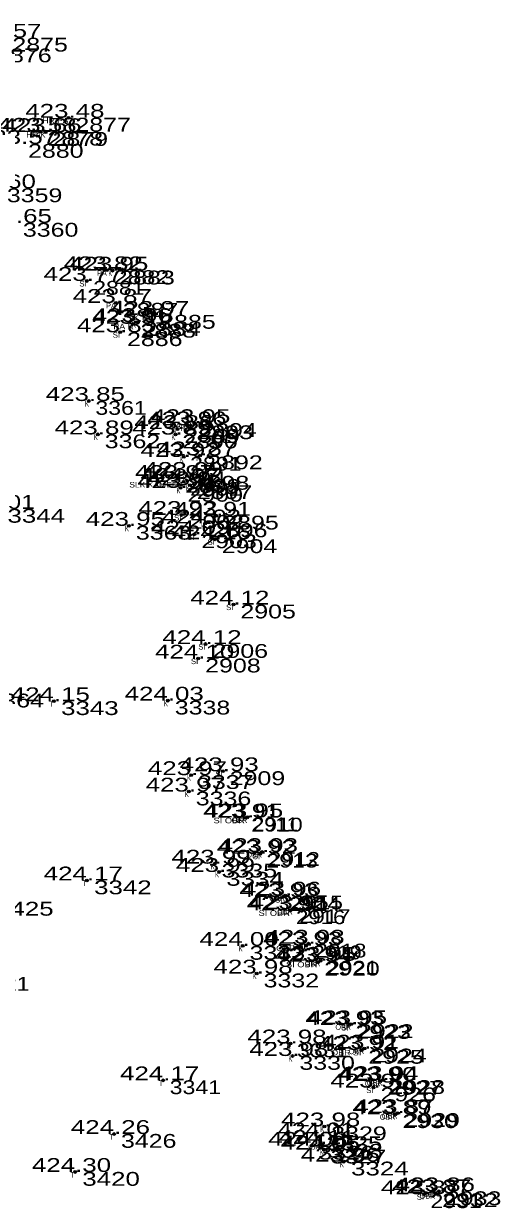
# Model space of a CAD drawing. Extents: x -639390 to -639074, y -1138747 to -1138358.
# Drawn here: x -639264.4 to -639238.5, y -1138459 to -1138394.7 of the extents above; entities that cross this region are included whole.
import ezdxf
from ezdxf.enums import TextEntityAlignment as Align

# ---------------------------------------------------------------- set-up
doc = ezdxf.new("R2010")
doc.units = 0
doc.header["$LTSCALE"] = 0.3
doc.header["$PDMODE"] = 32
doc.header["$PDSIZE"] = 0.15
for name, color, linetype in [('11', 7, 'Continuous'), ('12', 7, 'Continuous'), ('13', 7, 'Continuous'), ('57', 7, 'Continuous')]:
    doc.layers.add(name, color=color, linetype=linetype)

msp = doc.modelspace()

# ---------------------------------------------------------------- linework, layer by layer
at = {"layer": '11'}
for p in [(-639261.94, -1138399.83), (-639263.45, -1138400.59), (-639263.18, -1138400.61), (-639259.86, -1138408.1), (-639259.56, -1138408.12), (-639260.95, -1138408.68), (-639259.37, -1138409.87), (-639257.34, -1138410.52), (-639258.41, -1138411), (-639258.28, -1138410.91), (-639259.14, -1138411.46), (-639260.83, -1138415.19), (-639255.32, -1138416.51), (-639255.11, -1138416.39), (-639260.35, -1138417), (-639256.14, -1138417.01), (-639256.03, -1138416.71), (-639255.69, -1138418.22), (-639254.79, -1138418.14), (-639255.99, -1138419.42), (-639255.69, -1138419.58), (-639255.52, -1138419.25), (-639255.35, -1138419.76), (-639255.86, -1138419.9), (-639255.81, -1138421.37), (-639253.92, -1138421.41), (-639258.66, -1138421.96), (-639254.53, -1138421.83), (-639255.11, -1138422.42), (-639254, -1138422.69), (-639252.99, -1138426.23), (-639254.5, -1138428.37), (-639254.9, -1138429.16), (-639262.73, -1138431.47), (-639256.55, -1138431.44), (-639255.29, -1138435.48), (-639253.57, -1138435.27), (-639255.41, -1138436.37), (-639252.24, -1138437.77), (-639252.37, -1138437.79), (-639251.44, -1138439.65), (-639254.01, -1138440.28), (-639251.55, -1138439.74), (-639253.77, -1138440.73), (-639260.94, -1138441.19), (-639250.33, -1138442.09), (-639250.19, -1138442.01), (-639249.93, -1138442.81), (-639249.77, -1138442.75), (-639252.49, -1138444.74), (-639249.04, -1138444.72), (-639248.91, -1138444.62), (-639248.44, -1138445.6), (-639248.27, -1138445.55), (-639251.73, -1138446.24), (-639246.75, -1138449.03), (-639246.61, -1138448.99), (-639249.89, -1138450.03), (-639246.05, -1138450.38), (-639245.89, -1138450.31), (-639249.79, -1138450.71), (-639256.8, -1138452.03), (-639245.39, -1138452.42), (-639245.01, -1138452.06), (-639244.9, -1138452.02), (-639244.09, -1138453.81), (-639244.2, -1138453.87), (-639259.47, -1138454.94), (-639248.32, -1138455.07), (-639248.06, -1138454.53), (-639248.76, -1138455.58), (-639248.27, -1138455.48), (-639248.09, -1138455.79), (-639261.58, -1138457), (-639247, -1138456.44), (-639242.65, -1138458.21), (-639242.04, -1138458.15), (-639241.84, -1138458.05)]:
    msp.add_point(p, dxfattribs=at)

# ---------------------------------------------------------------- texts
at = {"layer": '12'}
for s, width, p in [('423.57 ', 1.4, (-639265.36, -1138395.49)), ('423.48 ', 1.4, (-639261.94, -1138399.83)), ('423.58 ', 1.4, (-639263.45, -1138400.59)), ('423.66 ', 1.4, (-639263.179, -1138400.61)), ('423.57 ', 1.4, (-639264.51, -1138401.25)), ('423.60 ', 1.4, (-639265.66, -1138403.66)), ('423.65 ', 1.4, (-639264.79, -1138405.53)), ('423.82 ', 1.4, (-639259.86, -1138408.1)), ('423.95 ', 1.4, (-639259.56, -1138408.12)), ('423.77 ', 1.4, (-639260.95, -1138408.68)), ('423.87 ', 1.4, (-639259.37, -1138409.87)), ('423.97 ', 1.4, (-639257.34, -1138410.52)), ('423.83 ', 1.4, (-639259.14, -1138411.46)), ('423.91 ', 1.35, (-639258.409, -1138411)), ('423.96 ', 1.4, (-639258.279, -1138410.91)), ('423.85 ', 1.4, (-639260.83, -1138415.19)), ('423.96 ', 1.4, (-639255.319, -1138416.51)), ('423.95 ', 1.4, (-639255.11, -1138416.39)), ('423.89 ', 1.4, (-639260.35, -1138417)), ('423.89 ', 1.4, (-639256.14, -1138417.01)), ('423.86 ', 1.4, (-639256.029, -1138416.71)), ('423.92 ', 1.4, (-639255.69, -1138418.22)), ('423.87 ', 1.4, (-639254.79, -1138418.14)), ('423.97 ', 1.4, (-639255.99, -1138419.42)), ('424.07 ', 1.4, (-639255.69, -1138419.58)), ('423.99 ', 1.4, (-639255.52, -1138419.25)), ('423.94 ', 1.4, (-639255.35, -1138419.76)), ('423.94 ', 1.4, (-639255.86, -1138419.9)), ('424.01 ', 1.35, (-639265.639, -1138421.04)), ('423.92 ', 1.4, (-639255.81, -1138421.37)), ('423.91 ', 1.35, (-639253.919, -1138421.41)), ('423.95 ', 1.4, (-639258.66, -1138421.96)), ('424.02 ', 1.4, (-639254.53, -1138421.83)), ('424.09 ', 1.4, (-639255.11, -1138422.42)), ('424.16 ', 1.4, (-639253.999, -1138422.69)), ('424.12 ', 1.4, (-639252.99, -1138426.23)), ('424.12 ', 1.4, (-639254.5, -1138428.37)), ('424.10 ', 1.4, (-639254.9, -1138429.16)), ('424.15 ', 1.4, (-639262.73, -1138431.47)), ('424.03 ', 1.4, (-639256.55, -1138431.44)), ('423.97 ', 1.4, (-639255.29, -1138435.48)), ('423.93 ', 1.4, (-639253.57, -1138435.27)), ('423.97 ', 1.4, (-639255.41, -1138436.37)), ('423.91 ', 1.35, (-639252.369, -1138437.79)), ('423.95 ', 1.4, (-639252.24, -1138437.77)), ('423.92 ', 1.4, (-639251.55, -1138439.74)), ('423.93 ', 1.4, (-639251.44, -1138439.65)), ('423.99 ', 1.4, (-639254.01, -1138440.28)), ('423.99 ', 1.4, (-639253.77, -1138440.73)), ('424.17 ', 1.4, (-639260.94, -1138441.19)), ('423.93 ', 1.4, (-639250.33, -1138442.09)), ('423.96 ', 1.4, (-639250.189, -1138442.01)), ('423.92 ', 1.4, (-639249.93, -1138442.81)), ('423.95 ', 1.4, (-639249.77, -1138442.75)), ('424.00 ', 1.4, (-639252.49, -1138444.74)), ('423.93 ', 1.4, (-639249.04, -1138444.72)), ('423.98 ', 1.4, (-639248.91, -1138444.62)), ('423.94 ', 1.4, (-639248.44, -1138445.6)), ('423.95 ', 1.4, (-639248.27, -1138445.55)), ('423.98 ', 1.4, (-639251.73, -1138446.24)), ('423.93 ', 1.4, (-639246.75, -1138449.03)), ('423.95 ', 1.4, (-639246.61, -1138448.99)), ('423.98 ', 1.4, (-639249.89, -1138450.03)), ('423.92 ', 1.4, (-639246.05, -1138450.38)), ('423.91 ', 1.35, (-639245.889, -1138450.31)), ('423.98 ', 1.4, (-639249.79, -1138450.71)), ('424.17 ', 1.4, (-639256.8, -1138452.03)), ('423.90 ', 1.4, (-639245.39, -1138452.42)), ('423.90 ', 1.4, (-639245.01, -1138452.06)), ('423.94 ', 1.4, (-639244.9, -1138452.02)), ('423.89 ', 1.4, (-639244.2, -1138453.87)), ('423.87 ', 1.4, (-639244.09, -1138453.81)), ('423.98 ', 1.4, (-639248.06, -1138454.53)), ('424.26 ', 1.4, (-639259.469, -1138454.94)), ('424.01 ', 1.35, (-639248.319, -1138455.07)), ('424.08 ', 1.4, (-639248.76, -1138455.58)), ('424.11 ', 1.35, (-639248.269, -1138455.48)), ('424.05 ', 1.4, (-639248.09, -1138455.79)), ('423.96 ', 1.4, (-639246.999, -1138456.44)), ('424.30 ', 1.4, (-639261.58, -1138457)), ('423.87 ', 1.4, (-639242.65, -1138458.21)), ('423.87 ', 1.4, (-639242.04, -1138458.15)), ('423.86 ', 1.4, (-639241.839, -1138458.05))]:
    msp.add_text(s, height=0.75, dxfattribs=dict(at, width=width)).set_placement(p, align=Align.CENTER)
at = {"layer": '13'}
for s, width, p in [(' 2875', 1.35, (-639265.36, -1138396.24)), (' 2876', 1.35, (-639266.24, -1138396.82)), (' 2877', 1.35, (-639261.94, -1138400.58)), (' 2878', 1.35, (-639263.45, -1138401.34)), (' 2879', 1.35, (-639263.18, -1138401.36)), (' 2880', 1.35, (-639264.51, -1138402)), (' 3359', 1.35, (-639265.66, -1138404.41)), (' 3360', 1.35, (-639264.79, -1138406.28)), (' 2882', 1.35, (-639259.86, -1138408.85)), (' 2883', 1.35, (-639259.56, -1138408.87)), (' 2881', 1.25, (-639260.95, -1138409.43)), (' 2887', 1.35, (-639259.37, -1138410.62)), (' 2885', 1.35, (-639257.34, -1138411.27)), (' 2888', 1.35, (-639258.41, -1138411.75)), (' 2884', 1.4, (-639258.28, -1138411.66)), (' 2886', 1.35, (-639259.14, -1138412.21)), (' 3361', 1.25, (-639260.83, -1138415.94)), (' 2893', 1.35, (-639255.32, -1138417.26)), (' 2894', 1.35, (-639255.11, -1138417.14)), (' 3362', 1.35, (-639260.35, -1138417.75)), (' 2890', 1.35, (-639256.14, -1138417.76)), (' 2889', 1.35, (-639256.03, -1138417.46)), (' 2891', 1.25, (-639255.69, -1138418.97)), (' 2892', 1.35, (-639254.79, -1138418.89)), (' 2899', 1.35, (-639255.99, -1138420.17)), (' 2901', 1.25, (-639255.69, -1138420.33)), (' 2898', 1.35, (-639255.52, -1138420)), (' 2900', 1.35, (-639255.86, -1138420.65)), (' 2897', 1.35, (-639255.35, -1138420.51)), (' 3344', 1.4, (-639265.64, -1138421.79)), (' 2902', 1.35, (-639255.81, -1138422.12)), (' 2895', 1.35, (-639253.92, -1138422.16)), (' 3363', 1.35, (-639258.66, -1138422.71)), (' 2896', 1.35, (-639254.53, -1138422.58)), (' 2903', 1.35, (-639255.11, -1138423.17)), (' 2904', 1.35, (-639254, -1138423.44)), (' 2905', 1.35, (-639252.99, -1138426.98)), (' 2906', 1.35, (-639254.5, -1138429.12)), (' 2908', 1.35, (-639254.9, -1138429.91)), (' 3364', 1.35, (-639266.66, -1138431.81)), (' 3343', 1.4, (-639262.73, -1138432.22)), (' 3338', 1.35, (-639256.55, -1138432.19)), (' 3337', 1.35, (-639255.29, -1138436.23)), (' 2909', 1.35, (-639253.57, -1138436.02)), (' 3336', 1.35, (-639255.41, -1138437.12)), (' 2910', 1.25, (-639252.37, -1138438.54)), (' 2911', 1.1, (-639252.24, -1138438.52)), (' 2912', 1.25, (-639251.44, -1138440.4)), (' 3335', 1.35, (-639254.01, -1138441.03)), (' 2913', 1.25, (-639251.55, -1138440.49)), (' 3334', 1.4, (-639253.77, -1138441.48)), (' 3342', 1.4, (-639260.94, -1138441.94)), (' 2914', 1.25, (-639250.33, -1138442.84)), (' 2915', 1.25, (-639250.19, -1138442.76)), (' 3425', 1.4, (-639266.26, -1138443.1)), (' 2916', 1.2, (-639249.93, -1138443.56)), (' 2917', 1.25, (-639249.77, -1138443.5)), (' 3333', 1.35, (-639252.49, -1138445.49)), (' 2919', 1.2, (-639249.04, -1138445.47)), (' 2918', 1.25, (-639248.91, -1138445.37)), (' 2920', 1.35, (-639248.44, -1138446.35)), (' 2921', 1.25, (-639248.27, -1138446.3)), (' 3421', 1.25, (-639267.19, -1138447.17)), (' 3332', 1.35, (-639251.73, -1138446.99)), (' 2923', 1.35, (-639246.75, -1138449.78)), (' 2922', 1.35, (-639246.61, -1138449.74)), (' 3331', 1.25, (-639249.89, -1138450.78)), (' 2925', 1.35, (-639246.05, -1138451.13)), (' 2924', 1.35, (-639245.89, -1138451.06)), (' 3330', 1.35, (-639249.79, -1138451.46)), (' 3341', 1.25, (-639256.8, -1138452.78)), (' 2926', 1.35, (-639245.39, -1138453.17)), (' 2927', 1.35, (-639245.01, -1138452.81)), (' 2928', 1.35, (-639244.9, -1138452.77)), (' 2930', 1.35, (-639244.2, -1138454.62)), (' 2929', 1.35, (-639244.09, -1138454.56)), (' 3426', 1.35, (-639259.47, -1138455.69)), (' 3325', 1.35, (-639248.32, -1138455.82)), (' 3329', 1.35, (-639248.06, -1138455.28)), (' 3326', 1.35, (-639248.76, -1138456.33)), (' 3328', 1.35, (-639248.27, -1138456.23)), (' 3327', 1.35, (-639248.09, -1138456.54)), (' 3324', 1.4, (-639247, -1138457.19)), (' 3420', 1.4, (-639261.58, -1138457.75)), (' 2931', 1.25, (-639242.65, -1138458.96)), (' 2932', 1.35, (-639242.04, -1138458.9)), (' 2933', 1.35, (-639241.84, -1138458.8))]:
    msp.add_text(s, height=0.75, dxfattribs=dict(at, width=width)).set_placement(p)
at = {"layer": '57'}
for s, width, p in [('HR PA', 1.15, (-639261.94, -1138400.13)), ('HR K', 1.1, (-639263.179, -1138400.91)), ('PA', 0.95, (-639263.45, -1138400.89)), ('PA', 0.95, (-639259.86, -1138408.4)), ('K', 0.65, (-639259.559, -1138408.42)), ('SI', 1.05, (-639260.95, -1138408.98)), ('PA', 0.95, (-639259.37, -1138410.17)), ('K PL', 1.25, (-639257.339, -1138410.82)), ('PA K', 1.2, (-639258.409, -1138411.3)), ('K', 0.65, (-639258.279, -1138411.21)), ('SI', 1.05, (-639259.14, -1138411.76)), ('K', 0.65, (-639260.829, -1138415.49)), ('KA PL', 1.2, (-639255.109, -1138416.69)), ('KA', 0.95, (-639255.32, -1138416.81)), ('K', 0.65, (-639260.349, -1138417.3)), ('K', 0.65, (-639256.139, -1138417.31)), ('K', 0.65, (-639256.029, -1138417.01)), ('K', 0.65, (-639255.689, -1138418.52)), ('K', 0.65, (-639254.789, -1138418.44)), ('SLK KAMERA', 1.15, (-639255.69, -1138419.88)), ('K', 0.65, (-639255.989, -1138419.72)), ('K', 0.65, (-639255.519, -1138419.55)), ('K', 0.65, (-639255.859, -1138420.2)), ('K', 0.65, (-639255.349, -1138420.06)), ('SI', 1.05, (-639255.81, -1138421.67)), ('K', 0.65, (-639253.919, -1138421.71)), ('K', 0.65, (-639258.659, -1138422.26)), ('K', 0.65, (-639254.529, -1138422.13)), ('SI', 1.05, (-639255.11, -1138422.72)), ('SI', 1.05, (-639254, -1138422.99)), ('SI', 1.05, (-639252.99, -1138426.53)), ('SI', 1.05, (-639254.5, -1138428.67)), ('SI', 1.05, (-639254.9, -1138429.46)), ('T', 0.85, (-639262.73, -1138431.77)), ('K', 0.65, (-639256.549, -1138431.74)), ('K', 0.65, (-639255.289, -1138435.78)), ('SI', 1.05, (-639253.57, -1138435.57)), ('K', 0.65, (-639255.409, -1138436.67)), ('SI OBR', 1.25, (-639252.369, -1138438.09)), ('OBR', 0.9, (-639252.239, -1138438.07)), ('K', 0.65, (-639254.009, -1138440.58)), ('OBR', 0.9, (-639251.439, -1138439.95)), ('SI', 1.05, (-639251.55, -1138440.04)), ('K', 0.65, (-639253.769, -1138441.03)), ('T', 0.85, (-639260.94, -1138441.49)), ('OBR', 0.9, (-639250.189, -1138442.31)), ('SI', 1.05, (-639250.33, -1138442.39)), ('SI OBR', 1.25, (-639249.929, -1138443.11)), ('OBR', 0.9, (-639249.769, -1138443.05)), ('K', 0.65, (-639252.489, -1138445.04)), ('OBR SI', 1.2, (-639249.04, -1138445.02)), ('OBR', 0.9, (-639248.909, -1138444.92)), ('SI OBR', 1.25, (-639248.439, -1138445.9)), ('OBR', 0.9, (-639248.269, -1138445.85)), ('K', 0.65, (-639251.729, -1138446.54)), ('OBR', 0.9, (-639246.609, -1138449.29)), ('SI', 1.05, (-639246.75, -1138449.33)), ('K', 0.65, (-639249.889, -1138450.33)), ('OBR SI', 1.2, (-639246.05, -1138450.68)), ('OBR', 0.9, (-639245.889, -1138450.61)), ('K', 0.65, (-639249.789, -1138451.01)), ('T', 0.85, (-639256.8, -1138452.33)), ('OBR', 0.9, (-639245.009, -1138452.36)), ('SI', 1.05, (-639245.39, -1138452.72)), ('OBR', 0.9, (-639244.899, -1138452.32)), ('OBR', 0.9, (-639244.199, -1138454.17)), ('OBR', 0.9, (-639244.089, -1138454.11)), ('T', 0.85, (-639259.47, -1138455.24)), ('K', 0.65, (-639248.059, -1138454.83)), ('K', 0.65, (-639248.759, -1138455.88)), ('SA', 0.95, (-639248.27, -1138455.78)), ('K', 0.65, (-639248.319, -1138455.37)), ('K', 0.65, (-639248.089, -1138456.09)), ('K', 0.65, (-639246.999, -1138456.74)), ('T', 0.85, (-639261.58, -1138457.3)), ('SI', 1.05, (-639242.65, -1138458.51)), ('OBR', 0.9, (-639242.039, -1138458.45)), ('OBR', 0.9, (-639241.839, -1138458.35))]:
    msp.add_text(s, height=0.3, dxfattribs=dict(at, width=width)).set_placement(p, align=Align.RIGHT)

doc.saveas('drawing.dxf')
